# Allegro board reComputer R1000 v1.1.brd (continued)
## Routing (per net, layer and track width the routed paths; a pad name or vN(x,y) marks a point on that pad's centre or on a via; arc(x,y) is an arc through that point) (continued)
N23572410: length 5.1
  TOP w0.121: Q4.4 31.3,73.57 30.48,74.38 C162.2 29.98,75.91 R162.2 R163.2
N23572413: length 2.1
  TOP w0.121: Q5.3 27.51,74.71 R163.1
N23578952: length 2
  BOTTOM w0.121: U31.3 34.01,73.37 R173.1
N23579284:
  vias: v1(85.5,22.67) v1(85.5,22.19) v1(85.5,21.7) v1(85.93,30.24) v1(85.93,29.76) v1(85.93,29.27) v1(85.96,22.67) v1(85.96,22.19) v1(85.96,21.7) v1(86.39,30.24) v1(86.39,29.76) v1(86.39,29.27)
N23611485: length 2.6
  BOTTOM w0.121: R12.1 77.3,37.39 U1.4
N23611490: length 2.7
  BOTTOM w0.305: C15.1 68.51,39.27 69.12,38.66 U1.6
N23612078: length 13.3
  LYR6 w0.381: v1(76.18,41.2) 71.3,41.2 67.95,44.55 v1(67.95,46.46)
  BOTTOM w0.381: U1.1 v1(76.18,41.2) ; C5.1 v1(67.95,46.46)
N23612081: length 1.5
  BOTTOM w0.381: R9.1 65.66,44.98 C5.2
N23613464: length 3.1
  BOTTOM w0.381: D10.2 67.17,42.72 R9.2
N23613978: length 4.8
  BOTTOM w0.121: U1.3 76.75,38.66 R10.2 77.59,37.9 77.9,38.21 78.66,38.21 R8.2
N23614867: length 6.2
  BOTTOM w0.305: C17.2 64.9,39.35 R13.2 66.65,39.35 R14.1 68.18,38.37 69.17,37.39 U1.5
N23615765: length 1.2
  BOTTOM w0.508: R11.2 65.64,47.95 C16.1
N23616333: length 7.5
  LYR6 w0.381: v1(48.52,42.62) 52.85,42.62 v1(53.75,41.72)
  BOTTOM w0.381: C18.1 v1(48.52,42.62) ; v1(53.75,41.72) 54.26,41.21 U2.1
N23616335: length 1.5
  BOTTOM w0.381: C18.2 46.35,42.6 R15.1
N23616337: length 1.9
  BOTTOM w0.381: R15.2 47.91,41.21 U2.8
N23616378: length 4.6
  BOTTOM w0.121: U2.3 56.33,38.67 R17.2 56.4,38.71 56.64,38.95 57.31,38.95 R16.2 57.61,38.33 R181.2
N23616505: length 1.7
  BOTTOM w0.121: R19.1 56.39,37.4 U2.4
N23616509: length 3.8
  BOTTOM w0.305: U2.5 49.22,37.4 48.87,37.06 R21.1 48.35,38.02 R20.2 48.36,38.37 48.08,38.65 C30.2
N23616593: length 2.8
  BOTTOM w0.305: C28.1 48.08,40.1 48.61,39.57 48.61,38.96 48.9,38.67 U2.6
N23616615: length 1.3
  BOTTOM w0.508: C29.1 43.72,48.49 R18.2
N23711005: length 11.5
  BOTTOM w0.114: J8.A2 105.6,60.78 105.71,60.9 106.41,60.9 106.83,60.48 106.83,59.61 107.58,58.86 109.24,58.86 110.12,59.74 111.9,59.74 112.37,59.27 D15.2 112.42,59.29 112.88,59.75 114.02,59.75 L4.3
N23711301: length 11.5
  BOTTOM w0.114: L4.2 114.07,60.03 112.88,60.03 112.42,60.49 D14.2 112.35,60.5 111.88,60.02 110,60.02 109.12,59.14 107.7,59.14 107.11,59.73 107.11,60.59 106.53,61.17 105.71,61.17 105.6,61.29 J8.A3
N23763799:
  vias: v1(111.18,17.16) v1(111.13,16.19) v1(112.27,16.19) v1(112.32,17.16) v1(113.31,16.17) v1(113.36,17.13) v1(114.28,17.13)
N23781625: length 1.4
  BOTTOM w0.121: U33.6 28.72,34.11 R651.2
N23800931: length 0.9
  BOTTOM w0.305: R13.1 65.68,38.49 R652.2
N23801005: length 1.9
  BOTTOM w0.305: R653.2 46.49,38.67 47.09,38.67 47.43,38.33 R20.1
N23858113: length 5.9
  BOTTOM w0.508: 2.49,51.98 2.55,52.04 J24.22
  BOTTOM w0.762: FB26.1 3.12,47.85 2.26,48.7 2.26,51.75 2.49,51.98
N23912708: length 39.1
  TOP w0.121: R24.2 48.87,65.9 49.91,64.86 50.29,64.86 v1(50.75,65.32) ; J4.28 v1(68.6,72.07)
  LYR3 w0.121: v1(68.6,72.07) v1(68.6,66.71)
  BOTTOM w0.121: v1(50.75,65.32) 51.93,64.13 57.38,64.13 59.97,66.73 68.59,66.73 v1(68.6,66.71)

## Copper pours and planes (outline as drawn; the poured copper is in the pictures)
3V3_RS485 on TOP: 62.84,25.06 62.21,25.06 61.95,25.31 61.95,27.32 62.23,27.6 63.1,27.6 63.27,27.42 63.27,26.99 63.1,26.81 63.1,25.31
3V3_RS485 on LYR6: 84,23.86 63.17,23.86 62.18,24.85 62.18,26.73 62.56,27.11 76.91,27.11 78.92,25.11 84,25.11 84.23,24.88 84.23,24.09
5V_ISO_INPUT on TOP: 72.06,19.67 72.06,18.2 71.86,18 71.86,17.06 71.73,16.93 70.92,16.93 70.64,17.21 70.64,18.25 70.11,18.78 69.7,18.78 69.27,19.21 69.27,21.37 69.52,21.63 70.39,21.63 70.82,21.2 70.82,19.67 71.07,19.42 71.73,19.42 71.99,19.67
5V_ISO_OUT on TOP: 68.15,11.87 67.44,11.87 66.37,12.94 64.9,12.94 64.52,13.32 64.52,14.54 64.77,14.79 65.15,14.79 65.89,14.06 67.08,14.06 68.4,12.74 68.4,12.13
5V_ISO_OUT on LYR6: 86.77,9.31 71.88,9.31 68.48,12.71 66.78,12.71 66.27,13.22 62.94,13.22 62.82,13.09 62.41,13.09 62.28,13.22 62.28,16.24 63.4,17.36 67.74,17.36 69.5,15.61 90.4,15.61 91.47,16.67 92.38,16.67 92.66,16.39 92.66,15.2
5V_TYPC on TOP: 65.08,10.65 64.06,10.65 63.43,10.02 62.66,10.02 62.18,10.5 62.18,11.72 61.52,12.38 61.52,12.99 61.42,13.09 60.68,13.09 60.51,12.92 60.51,12.41 61.11,11.8 61.11,9.99 61.39,9.71 61.65,9.71 62.13,9.23 63.65,9.23 64.47,10.04 65.08,10.04 65.2,10.17 65.2,10.53
5V_TYPC on TOP: 60.71,2.2 60.71,2.6 61.17,3.06 61.17,3.92 60.94,4.15 60.15,4.15 59.84,3.85 59.84,3.11 59.57,2.83 59.18,2.83 59.03,2.68 59.03,2.12 59.18,1.97 60.48,1.97
5V_TYPC on BOTTOM: 10.92,34.81 9.73,34.81 9.63,34.91 9.63,35.29 9.73,35.39 10.04,35.39 10.62,35.98 11.25,35.98 11.41,35.83 11.41,35.29
5V_TYPC on LYR3: 65.05,6.03 63.76,6.03 63.43,6.36 62.36,6.36 62.11,6.11 62.11,2.86 61.7,2.45 59.92,2.45 59.59,2.78 59.59,6.16 60.48,7.05 60.48,12.79 60.66,12.97 61.42,12.97 61.67,12.71 61.67,10.98 62.74,9.92 63.32,9.92 64.06,10.65 65,10.65 65.2,10.45 65.2,6.18
5V_TYPC on LYR3: 39.3,54.11 39.3,52.82 35.59,49.11 29.9,49.11 28.91,48.12 28.91,39.97 31.04,37.83 31.04,31.61 35.11,27.55 35.11,21.27 34.62,20.79 33.71,20.79 33.17,21.32 33.17,26.38 28.81,30.75 28.81,36.41 26.32,38.9 26.32,46.62 27.13,47.43 27.13,49.26 28.53,50.66 33.35,50.66 34.14,51.45 34.14,55.18 34.44,55.49 37.92,55.49
5V_TYPC on LYR6: 9.12,35.72 9.12,37.35 9.88,38.11 28.78,38.11 29.01,37.88 29.01,36.92 28.76,36.66 11.56,36.66 11.38,36.49 11.38,35.7 11.2,35.52 9.32,35.52
5V_TYPC on LYR6: 33.99,23.41 42.85,23.41 43.74,22.52 48.41,22.52 49.94,20.99 60.73,20.99 61.72,20 61.72,12.08 61.52,11.87 59.9,11.87 59.31,12.46 59.31,17.66 57.89,19.09 44.73,19.09 42.22,21.6 33.89,21.6 33.66,21.83 33.66,23.08 ; 1 cut-out
+1.8V_OUT on TOP: 34.57,69 54.38,69 56.57,71.18 56.57,72.15 56.42,72.3 56.26,72.3 54.43,70.47 46.76,70.47 46.15,69.86 34.62,69.86 34.42,69.66 34.42,69.15
+1.8V_OUT on BOTTOM: 56.72,71.77 56.72,72.88 56.49,73.11 56.14,73.11 55.96,72.94 55.96,71.77 56.11,71.61 56.57,71.61
GND on TOP: outline of 150 points within 1.88,1.1 117.43,83.4 ; 35 cut-outs
GND on TOP: 32.41,49.49 34.27,49.49 34.6,49.16 34.6,46.6 33.99,45.99 32.31,45.99 32.08,46.21 32.08,49.16
GND on TOP: 104.83,51.4 104.29,51.4 103.81,50.91 102.29,50.91 101.83,51.37 101.45,51.37 100.61,50.53 98.91,50.53 98.58,50.2 98.58,47.56 98.78,47.36 99.65,47.36 99.88,47.59 99.88,48.35 100.36,48.83 103.1,48.83 103.91,49.64 103.91,50.3 104.35,50.74 104.83,50.74 105.01,50.91 105.01,51.22
GND on TOP: 32.03,52.18 32.03,58 31.19,58.84 8.49,58.84 7.42,57.77 7.42,48.93 6.99,48.5 5.84,48.5 5.69,48.65 5.69,55.87 4.96,56.6 3.48,56.6 3.03,57.06 3.03,57.72 3.38,58.08 5.06,58.08 7.98,61 25.1,61 26.16,59.93 31.12,59.93 32.62,58.43 32.62,52.31 32.41,52.11 32.11,52.11
GND on BOTTOM: 36.4,46.72 34.17,46.72 33.35,45.91 32.57,45.91 32.36,46.11 32.36,47.26 33.99,48.88 36.55,48.88 36.68,48.75 36.68,47
GND on BOTTOM: outline of 126 points within 1.88,1.1 117.43,83.4 ; 25 cut-outs
GND on BOTTOM: 16.08,20.48 16.08,20.05 15.78,19.75 15.19,19.75 15.04,19.9 15.04,20.61 15.22,20.79 15.78,20.79
GND on LYR2_GND: outline of 130 points within 1.88,1.1 117.43,83.4
GND on LYR4_GND: outline of 136 points within 1.88,1.1 117.43,83.4
GND on LYR7_GND: outline of 124 points within 1.88,1.1 117.43,83.4
GND_EARTH on TOP: outline of 106 points within 0.23,0.22 119.48,83.4
GND_EARTH on TOP: 10.04,20.87 8.77,20.87 8.51,21.12 8.51,22.82 8.79,23.1 10.04,23.1 10.34,22.8 10.34,21.17
GND_EARTH on BOTTOM: outline of 114 points within 0.23,0.22 119.48,83.4 ; 1 cut-out
GND_EARTH on LYR2_GND, LYR3: outline of 89 points within 0.23,0.22 119.48,83.4 ; 1 cut-out
GND_EARTH on LYR4_GND: outline of 127 points within 0.23,0.22 119.48,83.4
GND_EARTH on LYR5_PWR: outline of 117 points within 0.23,0.22 119.48,83.4 ; 1 cut-out
GND_EARTH on LYR6: outline of 125 points within 0.23,0.22 119.48,83.4 ; 2 cut-outs
GND_EARTH on LYR7_GND: outline of 123 points within 0.23,0.22 119.48,83.4 ; 2 cut-outs
GND_ISO on TOP: 57.61,22.16 58.17,22.16 58.83,21.5 61.52,21.5 64.87,18.15 70.11,18.15 70.39,17.87 70.39,16.57 71.02,15.94 100.56,15.94 100.99,15.51 100.99,3.82 100.1,2.93 68.33,2.93 68.1,3.16 68.1,5.7 69.52,7.12 69.52,9.56 68.71,10.38 67.74,10.38 67.46,10.65 67.46,12.48 66.78,13.17 64.49,13.17 64.24,12.92 63.81,12.92 63.65,13.07 62.54,13.07 62.31,13.3 62.31,14.24 57.43,19.11 57.43,21.98 ; 1 cut-out
GND_ISO on TOP: 59.26,18.96 58.98,18.96 58.12,19.82 58.12,21.88 57.81,22.19 56.24,22.19 55.91,21.86 55.91,19.87 58.14,17.64 59.18,17.64 59.41,17.87 59.41,18.81
GND_ISO on BOTTOM: 57.61,22.16 58.17,22.16 58.83,21.5 61.52,21.5 64.87,18.15 70.11,18.15 70.39,17.87 70.39,16.57 71.02,15.94 100.56,15.94 100.99,15.51 100.99,3.82 100.1,2.93 68.33,2.93 68.1,3.16 68.1,5.7 69.52,7.12 69.52,9.56 68.71,10.38 67.74,10.38 67.46,10.65 67.46,12.48 66.78,13.17 64.49,13.17 64.24,12.92 63.81,12.92 63.65,13.07 62.54,13.07 62.31,13.3 62.31,14.24 57.43,19.11 57.43,21.98 ; 1 cut-out
GND_ISO on LYR2_GND, LYR4_GND, LYR5_PWR, LYR7_GND: 57.61,22.16 58.17,22.16 58.83,21.5 61.52,21.5 64.87,18.15 70.11,18.15 70.39,17.87 70.39,16.57 71.02,15.94 100.56,15.94 100.99,15.51 100.99,3.82 100.1,2.93 68.33,2.93 68.1,3.16 68.1,5.7 69.52,7.12 69.52,9.56 68.71,10.38 67.74,10.38 67.46,10.65 67.46,12.48 66.78,13.17 64.49,13.17 64.24,12.92 63.81,12.92 63.65,13.07 62.54,13.07 62.31,13.3 62.31,14.24 57.43,19.11 57.43,21.98
GND_ISO on LYR3: 57.61,22.16 58.17,22.16 58.83,21.5 61.52,21.5 64.87,18.15 70.11,18.15 70.39,17.87 70.39,16.57 71.02,15.94 99.32,15.94 100.99,14.26 100.99,3.82 100.1,2.93 68.33,2.93 68.1,3.16 68.1,5.7 69.52,7.12 69.52,9.56 68.71,10.38 67.74,10.38 67.46,10.65 67.46,12.48 66.78,13.17 64.49,13.17 64.24,12.92 63.81,12.92 63.65,13.07 62.54,13.07 62.31,13.3 62.31,14.24 57.43,19.11 57.43,21.98
VCC_USB1 on TOP: 98.24,53.49 97.94,53.78 97.94,54.65 98.05,54.75 98.48,54.75 98.76,55.03 98.76,55.18 100.59,57.01 102.03,57.01 102.31,56.73 102.31,56.35 101.48,55.51 101.48,55.03 99.94,53.49
VCC_USB1 on TOP: 110.75,73.72 110.75,73.93 109.45,75.22 109.45,75.68 109.3,75.83 108.1,75.83 107.88,75.6 107.88,74.74 109.12,73.49 110.52,73.49
VCC_USB1 on LYR3: 100,53.68 98.22,53.68 98.05,53.86 98.05,56.58 106.71,65.24 106.71,75.3 107.11,75.7 109.45,75.7 109.88,75.27 109.88,59.35 108.66,58.13 104.45,58.13
VCC_USB2 on TOP: 105.97,51.24 105.54,51.24 105.08,51.7 104.02,51.7 103.56,51.24 102.34,51.24 101.96,51.62 101.27,51.62 101.12,51.78 101.12,52.69 101.2,52.77 104.09,52.77 104.32,52.54 105.97,52.54 106.2,52.31 106.2,51.47
VCC_USB2 on TOP: 109.6,70.24 110.77,70.24 111.58,71.06 113.52,71.06 113.74,70.83 113.74,69.94 113.44,69.63 109.71,69.63 109.55,69.79 109.55,70.19
VCC_USB2 on LYR3: 101.27,52.82 105.97,52.82 106.99,53.83 106.99,55.87 112.6,61.48 112.6,69.07 111.74,69.94 111.74,70.47 111.91,70.65 114.1,70.65 114.35,70.4 114.35,60.06 109.4,55.1 109.4,52.06 108.56,51.22 101.37,51.22 101.12,51.47 101.12,52.67
VDD33_HUB1 on TOP: 43.21,33.79 42.65,33.79 42.34,34.1 42.34,36.59 42.7,36.94 44.66,36.94 44.91,36.69 44.91,35.98 44.76,35.83 43.46,35.83 43.31,35.67 43.31,35.09 43.49,34.91 43.49,34.07
VDD33_HUB1 on TOP: 59.16,27.42 59.16,28.89 58.98,29.07 58.37,29.07 58.22,28.92 58.22,27.34 58.45,27.11 58.85,27.11
VDD33_HUB1 on LYR6: 56.67,38.42 45.27,38.42 42.29,35.44 42.29,30.59 43.18,29.7 57.13,29.7 58.27,28.56 59.01,28.56 59.29,28.84 59.29,32.27 58.6,32.96 45.47,32.96 45.16,33.26 45.16,33.62 46.92,35.37 56.62,35.37 57,35.75 57,38.09
VDD33_HUB2 on TOP: 101.12,73.7 101.4,73.7 101.88,74.18 102.52,74.18 102.75,73.95 102.75,72.94 102.54,72.73 101.27,72.73 100.99,73.01 100.99,73.57
VDD33_HUB2 on LYR3: 94.49,65.26 100.43,65.26 102.67,67.5 102.67,73.24 102.34,73.57 98.45,73.57 97.36,74.66 96.07,74.66 91.93,70.52 87.81,70.52 86.62,71.72 86.62,74.46 86.16,74.92 77.07,74.92 76.66,74.51 76.66,73.14 76.96,72.83 81.38,72.83 86.87,67.35 92.41,67.35
VDD33A_HUB1 on TOP: 57.28,26.07 57.53,26.33 57.53,28.82 57.25,29.09 56.75,29.09 55.63,27.98 54.41,27.98 54.28,27.85 54.28,27.6 54.41,27.47 54.76,27.47 55.55,26.68 55.55,26.2 55.68,26.07
VDD33A_HUB1 on LYR3: 57.36,28.46 56.59,28.46 55.55,29.5 55.55,32.55 55.76,32.75 56.77,32.75 57.53,31.99 57.53,28.64
VDD33A_HUB1 on LYR6: 46.13,25.46 45.32,25.46 45.16,25.62 45.16,26.66 47.2,28.69 52.56,28.69 52.91,28.33 55.83,28.33 56.44,28.94 57.48,28.94 57.74,28.69 57.74,26.53 56.21,25.01 51.26,25.01 51.11,25.16 51.11,25.54 50.88,25.77 46.43,25.77
VDD_3V3_PCIE on TOP: 20.78,68.97 20.78,69.73 20.63,69.89 19.71,69.89 19.56,69.73 19.56,68.95 19.74,68.77 20.58,68.77
VDD_3V3_PCIE on BOTTOM: 21.39,65.54 19.43,65.54 19.38,65.59 19.38,70.07 19.66,70.34 21.36,70.34 21.59,70.12 21.59,65.75
VDD_3V3_PCIE on BOTTOM: 19.2,47.48 19.2,48.53 21.74,51.07 21.74,52.62 21.54,52.82 16.92,52.82 16.28,52.18 16.28,50.13 15.06,48.91 15.06,47.64 15.39,47.31 19.03,47.31
VDD_3V3_PCIE on LYR3: 18.77,48.68 16.49,48.68 15.65,49.52 15.65,68.54 17.15,70.04 20.42,70.04 20.6,69.86 20.6,50.51
VDD_3V3_SYS on TOP: 74.37,24.83 72.29,24.83 72.06,25.06 72.06,25.77 72.27,25.97 74.32,25.97 74.53,25.77 74.53,24.98
VDD_3V3_SYS on TOP: 63.81,26.94 63.81,27.57 64.01,27.77 64.67,27.77 64.85,27.6 64.85,26.89 64.7,26.73 64.01,26.73
VDD_3V3_SYS on TOP: 15.05,5.35 15.05,6.31 15.2,6.46 16.39,6.46 16.51,6.34 16.51,5.3 16.31,5.09 15.31,5.09
VDD_3V3_SYS on TOP: 102.19,75.78 101.96,75.55 101.96,75.07 102.11,74.92 102.67,74.92 103.15,74.43 104.02,74.43 104.22,74.64 104.22,75.55 103.99,75.78
VDD_3V3_SYS on TOP: 27.59,70.95 23.42,70.95 23.17,70.7 23.17,70.12 23.35,69.94 25.89,69.94 25.99,70.04 25.99,70.22 26.16,70.4 26.8,70.4 27.16,70.75 27.59,70.75 27.66,70.83 27.66,70.88
VDD_3V3_SYS on TOP: 43.89,30.75 43.89,32.8 43.64,33.06 42.47,33.06 42.19,32.78 42.19,30.72 42.42,30.49 43.64,30.49
VDD_3V3_SYS on BOTTOM: 5.39,45.3 4.52,45.3 3.99,45.83 3.99,46.44 3.71,46.72 3.05,46.72 2.82,46.49 2.82,45.86 3.25,45.43 3.25,43.8 3.51,43.55 5.21,43.55 5.44,43.78 5.44,45.25
VDD_3V3_SYS on BOTTOM: 41.76,27.85 41.76,29.12 41.43,29.45 40.39,29.45 40.03,29.09 40.03,27.9 40.26,27.67 41.58,27.67
VDD_3V3_SYS on BOTTOM: 13.95,48.58 12.83,48.58 11.53,47.28 11.53,46.11 11.94,45.71 13.92,45.71 14.18,45.96 14.18,48.35
VDD_3V3_SYS on BOTTOM: 17.12,18.5 15.37,18.5 15.22,18.66 15.22,18.81 16.41,20 16.41,20.41 16.56,20.56 17.38,20.56 17.58,20.36 17.58,18.96
VDD_3V3_SYS on BOTTOM: 56.44,44.12 54.71,44.12 54.41,44.43 54.41,49.02 55.37,49.99 62.21,49.99 62.61,49.58 62.61,47.14 62.23,46.76 57.53,46.76 56.77,46 56.77,44.45
VDD_3V3_SYS on LYR5_PWR: outline of 84 points within 2.29,4.96 110.19,80.89
VDD_5V_OUT on TOP: 36.91,79.21 36.91,79.95 36.73,80.12 36.02,80.12 33.71,82.43 31.8,82.43 31.4,82.03 31.4,80.63 33.12,78.9 36.6,78.9
VDD_5V_OUT on BOTTOM: 33.91,74.97 36.38,74.97 36.68,75.27 36.68,75.55 36.93,75.81 36.93,79.74 36.68,80 34.67,80 33.71,79.03 33.71,75.17
VDD_5V_SYS on TOP: 56.44,75.46 56.44,76.14 56.16,76.42 52.38,76.42 51.79,77 51.79,78.96 52.17,79.34 53.75,79.34 54.51,78.57 56.75,78.57 57.99,77.33 58.63,77.33 58.73,77.23 58.73,75.51 58.63,75.41 58.45,75.41 58.45,76.12 58.42,76.15 58.37,76.15 58.35,76.12 58.35,75.41 58.04,75.41 58.04,76.12 58.02,76.15 57.97,76.15 57.94,76.12 57.94,75.41 57.66,75.41 57.66,76.12 57.64,76.15 57.58,76.15 57.56,76.12 57.56,75.41 57.25,75.41 57.25,76.12 57.23,76.15 57.18,76.15 57.15,76.12 57.15,75.41 56.85,75.41 56.85,76.12 56.82,76.15 56.77,76.15 56.75,76.12 56.75,75.41 56.49,75.41
VDD_5V_SYS on TOP: 110.67,72.76 109.35,72.76 108.99,73.11 108.38,73.11 108.16,72.88 108.16,72.12 108.44,71.84 108.99,71.84 109.35,72.2 110.67,72.2 110.77,72.3 110.77,72.66
VDD_5V_SYS on TOP: 99.98,52.84 100.74,52.84 100.84,52.74 100.84,51.95 100.69,51.8 100.05,51.8 99.88,51.98 99.88,52.74
VDD_5V_SYS on TOP: 72.14,21.68 71.66,21.68 70.61,22.72 69.95,22.72 69.62,23.05 69.62,25.49 69.83,25.69 70.69,25.69 70.89,25.49 70.89,24.01 71.27,23.63 72.01,23.63 72.24,23.41 72.24,21.78
VDD_5V_SYS on BOTTOM: 100.74,52.84 99.67,52.84 99.21,52.39 98.07,52.39 92.76,57.7 82.02,57.7 81.66,57.34 81.66,54.29 81.92,54.04 93.02,54.04 97.16,49.9 100.41,49.9 100.89,50.38 100.89,52.69
VDD_5V_SYS on BOTTOM: 76.28,43.88 74.96,43.88 74.55,44.28 74.55,48.3 75.92,49.67 81.59,49.67 82.22,49.03 82.22,47.61 81.97,47.36 81.38,47.36 80.67,46.65 77.09,46.65 76.76,46.32 76.76,44.36
VDD_5V_SYS on BOTTOM: 107.39,72.66 107.39,75.07 107.65,75.32 108.69,75.32 108.87,75.15 108.87,73.52 109.32,73.06 109.32,72.73 110.19,71.87 110.19,71.31 110.04,71.16 108.89,71.16
VDD_5V_SYS on BOTTOM: 27.16,73.85 26.62,73.85 25.5,74.97 25.1,74.97 24.79,74.66 24.79,74.08 25.94,72.94 27.21,72.94 27.38,73.11 27.38,73.62
VDD_5V_SYS on BOTTOM: 5.41,37.45 5.08,37.78 5.08,38.8 5.39,39.1 9.02,39.1 10.44,37.68 10.44,36.26 9.98,35.8 9.73,35.8 9.6,35.93 9.6,36.64 8.79,37.45
VDD_5V_SYS on LYR3: 6.43,38.21 6.43,41.92 15.04,50.53 15.04,68.9 18.7,72.55 18.7,73.32 18.37,73.65 15.7,73.65 10.87,68.82 10.87,50.41 4.37,43.9 4.37,38.21 4.73,37.86 6.07,37.86
VDD_5V_SYS on LYR3: 80.39,47.84 80.39,67.45 80.83,67.88 83.54,67.88 83.95,67.47 83.95,47.81 83.64,47.51 80.72,47.51
VDD_5V_SYS on LYR5_PWR: 81.69,56.45 81.69,57.97 82.22,58.51 98.43,58.51 99.93,60.01 99.93,68.13 101.09,69.3 102.8,69.3 103.41,69.91 103.41,71.84 104.83,73.27 108.97,73.27 109.53,72.71 109.53,66.46 110.54,65.44 114.45,65.44 117.25,62.65 117.25,59.5 115.8,58.05 105.49,58.05 103.63,56.2 81.94,56.2
VDD_5V_SYS on LYR5_PWR: 80.98,49.54 77.8,49.54 77.24,48.98 77.24,38.75 69.27,30.77 69.27,25.08 69.67,24.68 71.17,24.68 71.55,25.06 71.55,26.43 72.11,26.99 74.58,26.99 81.41,33.82 81.41,49.11
VDD_5V_SYS on LYR5_PWR: 82.6,66.59 78.11,66.59 77.68,67.02 77.68,68.13 76.23,69.58 43.94,69.58 42.06,67.7 37.21,67.7 33.68,71.23 17.88,71.23 17.17,71.94 17.17,75.7 19.87,78.4 65.03,78.4 68.84,74.59 70.44,74.59 70.45,74.57 79.75,74.57 82.98,71.34 82.98,66.97
VDD_IN on TOP: 67.54,30.59 67.24,30.59 67.06,30.42 67.06,26.96 67.59,26.43 71.25,26.43 71.81,26.99 71.81,30.09 71.27,30.62 69.78,30.62 69.6,30.44 69.6,28.23 69.55,28.18 69.09,28.18 69.04,28.23 69.04,30.47 68.89,30.62 68.48,30.62 68.33,30.47 68.33,28.28 68.25,28.21 67.87,28.21 67.77,28.31 67.77,30.36
VDD_IN on TOP: 29.39,76.31 29.85,76.31 30,76.47 30.89,76.47 31.22,76.14 31.22,74.79 31.47,74.54 32.46,74.54 32.57,74.64 32.57,75.04 32.46,75.15 31.85,75.15 31.8,75.2 31.8,75.75 31.85,75.81 32.46,75.81 32.57,75.91 32.57,76.31 32.46,76.42 31.88,76.42 31.83,76.47 31.83,77.02 31.93,77.13 32.51,77.13 32.59,77.2 32.59,78.85 32.24,79.21 29.87,79.21 29.24,78.57 29.24,76.47
VDD_IN on BOTTOM: 17.33,80.05 18.52,80.05 18.85,80.38 18.85,81.34 18.57,81.62 17.27,81.62 17.07,81.42 17.07,80.3
VDD_IN on BOTTOM: 64.8,53.33 42.37,53.33 42.24,53.45 42.24,53.89 44.58,56.22 55.45,56.22 56.31,55.36 64.8,55.36 65.05,55.1 65.05,53.58
VDD_IN on BOTTOM: 54.28,40.25 55.7,40.25 56.09,40.63 57.1,40.63 57.3,40.83 62.38,40.83 62.69,40.52 62.69,39.33 62.51,39.15 59.16,39.15 58.93,38.92 58.93,38.42 58.8,38.29 58.65,38.29 58.45,38.49 58.45,38.9 58.19,39.15 55.91,39.15 55.4,39.66 54.23,39.66 54.13,39.76 54.13,40.09
VDD_IN on BOTTOM: 74.83,40.22 76.25,40.22 76.43,40.4 85.83,40.4 86.24,39.99 86.24,38.11 85.63,37.5 80.06,37.5 79.86,37.71 79.86,38.14 79.56,38.44 77.29,38.44 76.1,39.64 74.81,39.64 74.68,39.76 74.68,40.07
VDD_IN on LYR3: 64.65,39.18 61.62,39.18 61.42,39.38 61.42,42.91 62.28,43.78 62.28,53.61 62.49,53.81 64.65,53.81 64.82,53.63 64.82,53.05 65.18,52.69 65.18,39.71
VDD_IN on LYR3: 31.96,79.21 34.93,79.21 39.19,74.94 39.19,71.72 43.21,67.7 43.21,53.58 42.93,53.3 40.85,53.3 40.49,53.66 40.49,65.14 34.88,70.75 34.88,71.59 31.52,74.94 31.52,78.78
VDD_IN on LYR6: 83.44,36.16 79.07,36.16 78.34,35.42 78.34,29.3 77.65,28.61 60.76,28.61 59.21,30.16 59.21,40.27 59.69,40.75 63.91,40.75 64.42,40.25 64.42,37.65 64.72,37.35 65.56,37.35 67.77,39.56 83.31,39.56 83.85,39.03 83.85,36.56
VDD_IN on LYR6: 32.21,79.11 21.14,79.11 18.87,81.37 17.22,81.37 16.97,81.11 16.97,79.16 19.76,76.36 32.31,76.36 32.59,76.64 32.59,78.73
VDD_LTE_3V3 on TOP: 77.93,30.97 77.93,29.91 76.94,28.92 76,28.92 75.44,28.36 75.44,27.04 75.16,26.76 73.51,26.76 73.26,27.01 73.26,29.09 74.15,29.98 74.73,29.98 75.82,31.08 75.82,31.97 79.4,35.55 79.4,36.03 79.53,36.16 80.85,36.16 81.1,35.9 81.1,34.15
VDD_LTE_3V3 on TOP: 106.53,31.99 106.53,33.82 106.76,34.05 108,34.05 108.26,33.79 108.26,31.97 108.1,31.81 106.71,31.81
VDD_LTE_3V3 on TOP: 33.56,65.19 35.71,65.19 35.97,65.44 35.97,66 35.84,66.13 33.61,66.13 33.35,65.87 33.35,65.39
VDD_LTE_3V3 on BOTTOM: 107.34,33.08 104.27,33.08 103.1,34.25 103.1,35.98 103.33,36.21 103.84,36.21 104.7,35.34 108.18,35.34 108.31,35.22 108.31,34.73 108.21,34.63 107.75,34.63 107.5,34.38 107.5,33.24
VDD_LTE_3V3 on BOTTOM: 80.11,36.13 79.61,36.13 79.02,35.55 79.02,33.92 79.23,33.72 80.06,33.72 80.29,33.95 80.29,35.95
VDD_LTE_3V3 on LYR3: 78.72,33.72 78.36,34.07 78.36,44.51 75.49,47.38 75.49,66.79 75.8,67.09 78.72,67.09 79,66.81 79,48.75 81.18,46.57 81.18,34.96 79.94,33.72
VDD_LTE_3V3 on LYR5_PWR: 42.98,65.14 34.95,65.14 34.57,65.52 34.57,67.02 34.9,67.35 42.34,67.35 44.25,69.25 75.82,69.25 77.19,67.88 77.19,66.92 76.86,66.59 75.47,66.59 75.11,66.94 44.78,66.94
VDD_LTE_3V3 on LYR6: 79.58,25.62 107.32,25.62 108.49,26.78 108.49,34.76 107.55,35.7 79.4,35.7 78.97,35.27 78.97,26.22
VDD_OUT on TOP: 35.44,77.66 36.43,77.66 37.29,78.52 37.29,79.95 36.53,80.71 36.53,81.93 37.01,82.41 38.86,82.41 39.32,81.95 39.32,74.13 38.48,73.29 35.21,73.29 34.62,73.88 34.62,76.85
VDD_OUT on BOTTOM: 37.54,76.47 37.54,75.7 37.82,75.42 39.6,75.42 40.72,76.54 40.72,78.7 40.52,78.9 40.21,78.9 40.03,78.73 40.03,76.57 39.96,76.49 39.55,76.49 39.45,76.59 39.45,79.41 38.84,80.02 37.82,80.02 37.49,79.69 37.49,76.52
VDD_UPS on TOP: 67.08,32.37 67.08,35.32 67.74,35.98 71.55,35.98 73.46,37.88 75.52,37.88 78.35,40.72 78.35,43.43 78.74,43.83 83.09,43.83 83.49,43.42 83.49,40.45 79.48,36.44 78.67,36.44 75.16,32.93 73.79,32.93 73.05,32.19 69.78,32.19 69.6,32.37 69.6,34.51 69.55,34.56 69.12,34.56 69.04,34.48 69.04,32.35 68.89,32.19 68.43,32.19 68.33,32.3 68.33,34.53 68.28,34.58 67.87,34.58 67.77,34.48 67.77,32.35 67.62,32.19 67.26,32.19
VDD_UPS on BOTTOM: 82.65,41.46 82.43,41.69 82.43,44.13 83.04,44.74 83.9,44.74 84.03,44.87 84.03,48.14 84.48,48.6 87.53,48.6 87.94,48.2 87.94,42.89 86.51,41.46
EXT_VCC_9_36V on TOP: 96.67,31.1 90.86,31.1 90.4,31.56 90.4,36.44 91.19,37.22 92.61,37.22 94.03,38.65 94.03,41.49 94.62,42.07 97.16,42.07 97.67,41.57 97.67,32.09
EXT_VCC_9_36V on BOTTOM: 97.41,40.55 95.48,40.55 91.7,44.33 91.7,45.15 91.26,45.58 88.98,45.58 88.85,45.71 88.85,46.11 88.95,46.21 89.56,46.21 89.61,46.27 89.61,46.8 89.56,46.85 88.9,46.85 88.83,46.93 88.83,47.36 88.95,47.48 89.56,47.48 89.64,47.56 89.64,48.04 89.56,48.12 89,48.12 88.83,48.3 88.83,48.78 89.03,48.98 91.98,48.98 92.38,48.58 92.38,47.23 92.71,46.9 94.24,46.9 97.67,43.47 97.67,40.8
EXT_VCC_9_36V on LYR3: 105.51,17.56 105.51,23.99 96.04,33.46 95.07,33.46 94.62,33.01 94.62,27.37 99.77,22.21 99.77,17.44 100.38,16.83 104.78,16.83
HDMI0_5V on TOP: 98.38,47.46 98.38,51.17 98.2,51.35 97.18,51.35 97.03,51.19 97.03,47.48 97.28,47.23 98.15,47.23
HDMI0_5V on LYR3: 101.27,41.21 98.3,41.21 95.56,43.95 95.56,48.09 95.96,48.5 97.69,48.5 97.89,48.3 97.89,47.43 97.34,46.87 97.34,44.67 98.22,43.78 101.42,43.78 101.7,43.5 101.7,41.64
ISO_5V on TOP: 58.98,16.5 65.23,16.5 65.43,16.29 65.43,15.63 65.23,15.43 58.88,15.43 58.7,15.61 58.7,16.22
LORA_3V3 on BOTTOM: 53.52,23.79 53.52,27.8 53.32,28 53.11,28 52.99,27.88 52.99,26.1 52.94,26.05 52.76,26.05 52.71,26.1 52.71,27.85 52.58,27.98 52.35,27.98 52.17,27.8 52.17,26.1 50.55,24.47 50.55,23.68 50.78,23.46 53.19,23.46
LORA_3V3 on BOTTOM: 71.02,34.12 71.02,36.66 71.17,36.82 71.63,36.82 72.16,36.28 72.16,32.93 71.53,32.3 59.26,32.3 58.98,32.57 58.98,36.05 59.13,36.21 59.34,36.21 59.51,36.03 59.51,34.07 59.82,33.77 70.67,33.77
LORA_3V3 on BOTTOM: 42.98,26.91 40.59,26.91 40.39,26.71 40.39,25.95 40.64,25.69 43,25.69 43.23,25.92 43.23,26.66
LORA_3V3 on LYR5_PWR: 51.31,23.35 42.04,23.35 41.48,23.91 41.48,26.94 44.02,29.48 44.02,35.39 44.25,35.62 59.64,35.62 59.97,35.29 59.97,33.62 51.69,25.34 51.69,23.74
POE_12V on TOP: 35.84,44.87 31.35,44.87 27.66,41.19 27.66,39.79 28.32,39.13 34.83,39.13 36.3,40.6 36.3,44.41
POE_12V on BOTTOM: 54.76,50.74 54.21,50.18 43.49,50.18 40.36,47.05 40.36,44.41 38.03,42.07 34.32,42.07 33.58,42.81 33.58,45.68 34.27,46.37 36.78,46.37 37.06,46.65 37.06,48.45 41.63,53.02 92.84,53.02 95.1,50.76 95.1,47.74 94.62,47.26 93.04,47.26 92.69,47.61 92.69,49.57 91.52,50.74
POE_IN_N on TOP: 11.61,9.64 12.6,9.64 12.96,9.28 14.46,9.28 14.73,9 14.73,7.78 14.28,7.33 11.51,7.33 11.23,7.61 11.23,9.26
POE_IN_N on TOP: 23.07,16.22 19.99,16.22 19.74,16.47 19.74,17.74 20.27,18.27 21.95,18.27 23.07,19.39 23.07,21.91 23.4,22.24 25.86,22.24 26.16,21.93 26.16,19.19 25.33,18.35 25.2,18.35
POE_IN_N on TOP: 30.74,17.18 30.74,15.12 31.32,14.54 33.78,14.54 34.19,14.95 34.19,17.28 33.71,17.77 31.32,17.77
POE_IN_N on BOTTOM: 26.67,18.33 25.45,18.33 25.15,18.63 25.15,19.77 25.35,19.98 26.7,19.98 26.9,19.77 26.9,18.55
POE_IN_N on LYR3: 33.66,14.57 33.25,14.57 31.35,16.47 26.37,16.47 25,17.84 25,19.72 25.25,19.98 27.03,19.98 28.17,18.83 33.51,18.83 33.99,18.35 33.99,14.9
POE_IN_N on LYR6: 21.11,17.94 19.54,17.94 19.23,17.64 19.23,16.17 18.98,15.91 15.29,15.91 12,12.62 12,8.58 12.42,8.17 14.73,8.17 15.09,8.52 15.09,10.38 18.18,13.46 19.52,13.46 21.36,15.3 21.36,17.69
POE_IN_N1 on TOP: 40.01,15.33 36.15,15.33 34.85,16.62 34.85,23.05 33.76,24.14 28.43,24.14 27.94,24.62 27.94,25.67 28.3,26.02 36.25,26.02 37.32,24.95 37.32,20.31 40.44,17.18 40.44,15.76
POE_IN_P on TOP: 20.98,15.07 21.57,15.66 23.37,15.66 24.67,16.95 24.67,18.05 25.07,18.45 25.86,18.45 26.06,18.25 26.06,14.44 25.3,13.68 18.37,13.68 14.35,9.66 13.16,9.66 12.58,10.25 10.42,10.25 9.98,9.82 9.98,8.88 9.5,8.39 9.1,8.39 8.82,8.67 8.82,11.77 10.39,13.35 15.85,13.35 17.05,14.54 17.91,14.54 18.44,15.07
POE_IN_P1 on TOP: 38.08,21.78 38.08,25.64 37.06,26.66 27.43,26.66 26.44,27.65 13.41,27.65 12.22,26.45 12.22,24.78 11.66,24.22 8.18,24.22 7.62,24.78 7.62,25.82 10.92,29.12 37.72,29.12 41.63,25.21 41.63,21.86 41.15,21.37 38.48,21.37
UART_3V3 on TOP: 60.63,5.57 60.63,7.1 60.4,7.33 58.45,7.33 58.24,7.12 58.24,6.31 58.37,6.18 58.73,6.18 59.57,5.35 60.4,5.35
USBA_GND on TOP: 105.41,65.21 114.23,65.21 114.71,65.7 115.27,65.7 115.55,65.42 115.55,64.15 115.27,63.87 105.39,63.87 105.13,64.12 105.13,64.93
USBA_GND on BOTTOM: 115.32,65.77 114.81,65.77 114.1,65.06 114.1,63.87 114.48,63.49 115.17,63.49 115.55,63.87 115.55,65.54
USIM_1V8 on TOP: 33.25,67.04 31.68,67.04 31.42,67.3 31.42,68.39 31.73,68.69 32.79,68.69 33.1,69 33.1,69.35 33.23,69.48 33.94,69.48 34.11,69.3 34.11,68.85 33.56,68.29 33.56,67.35
USIM_VDD on TOP: 31.78,55.97 31.78,57.75 31.57,57.95 31.09,57.95 30.84,57.7 30.84,55.99 31.07,55.76 31.57,55.76
N21116206 on BOTTOM: 102.77,24.78 106.94,24.78 109.45,22.26 112.12,22.26 112.68,21.7 112.68,19.85 110.09,17.26 110.09,9.36 108.79,8.06 108.79,6.57 108.44,6.21 107.47,6.21 107.06,6.62 107.06,9.41 107.6,9.94 107.6,18.73 105.64,20.69 102.72,20.69 102.01,21.4 102.01,24.01
N21116211 on TOP: 80.6,21.2 79.23,21.2 78.01,22.41 76.25,22.41 75.87,22.8 75.87,24.75 76.43,25.31 78.39,25.31 80.62,27.55 109.45,27.55 110.14,28.23 110.14,35.01 110.77,35.65 113.01,35.65 113.29,35.37 113.29,34.48 112.63,33.82 112.63,24.95 112.12,24.45 82.6,24.45 81.21,23.05 81.21,21.81
N21116390 on TOP: 84.08,16.73 85.47,16.73 86.74,18 89.54,18 90.25,17.28 95,17.28 95.48,17.77 95.48,19.77 94.97,20.28 85.52,20.28 83.54,18.3 83.54,17.26
N21116390 on BOTTOM: 92,19.49 97.61,19.49 99.37,21.25 99.37,23.86 98.55,24.68 97.31,24.68 94.72,22.08 91.82,22.08 91.39,21.65 91.39,20.1
N21392725 on BOTTOM: 4.42,36.05 9.22,36.05 9.35,35.93 9.35,34.2 9.12,33.97 7.8,33.97 6.96,34.81 4.45,34.81 4.24,35.01 4.24,35.88
N21411651 on TOP: 58.96,20.08 60.84,20.08 61.78,19.14 67.41,19.14 67.74,19.47 67.74,21.53 67.34,21.93 66.6,21.93 66.3,21.63 66.3,21.17 65.97,20.84 62.44,20.84 61.72,21.55 58.88,21.55 58.6,21.27 58.6,20.43
N21629438 on TOP: 96.75,43.8 96.75,46.77 96.4,47.13 94.9,47.13 94.64,46.87 94.64,43.88 94.92,43.6 96.55,43.6
N22027038 on TOP: 22.58,23.38 21.92,23.38 21.72,23.58 21.72,25.34 23.78,27.39 24.11,27.39 24.34,27.16 24.34,26.4 22.79,24.85 22.79,23.58
N22027038 on TOP: 20.42,19.75 20.42,18.71 20.58,18.55 21.47,18.55 21.92,19.01 21.92,19.75 21.74,19.93 20.6,19.93
N22027038 on BOTTOM: 22.13,22.24 21.54,22.24 21.36,22.41 21.36,23.71 21.64,23.99 22.48,23.99 22.66,23.81 22.66,23.48 22.3,23.13 22.3,22.41
N22027038 on LYR3: 21.82,18.76 21.11,18.76 20.88,18.99 20.88,21.86 21.67,22.64 21.67,23.74 21.85,23.91 22.74,23.91 22.96,23.68 22.96,22.39 22.13,21.55 22.13,19.06
N22027110 on TOP: 8.87,18.38 9.91,18.38 10.06,18.53 10.06,19.72 9.91,19.87 8.87,19.87 8.69,19.7 8.69,18.55
N22027110 on TOP: 17.71,22.34 17.05,22.34 16.84,22.54 16.84,26.45 17.86,27.47 18.34,27.47 18.47,27.34 18.47,26.48 17.96,25.97 17.96,22.59
N22027110 on LYR6: 9.53,19.19 8.92,19.19 8.69,19.42 8.69,20.84 11.58,23.74 12.4,23.74 12.91,24.24 17.66,24.24 17.96,23.94 17.96,22.72 17.55,22.31 12.65,22.31
N22027117 on TOP: 20.96,22.31 20.3,22.31 20.09,22.52 20.09,26.63 20.91,27.44 21.29,27.44 21.41,27.32 21.41,26.45 21.21,26.25 21.21,22.57
N22027117 on TOP: 16.72,19.75 16.72,18.71 16.87,18.55 18.06,18.55 18.21,18.71 18.21,19.75 18.04,19.93 16.89,19.93
N22027117 on LYR3: 21.01,23.66 18.95,23.66 18.49,23.2 18.49,22.44 17.43,21.37 17.43,18.99 17.66,18.76 18.72,18.76 18.95,18.99 18.95,21.27 20.3,22.62 20.91,22.62 21.14,22.85 21.14,23.53
N22028382 on TOP: 14.46,22.19 13.79,22.19 13.59,22.39 13.59,26.07 14.84,27.32 15.09,27.32 15.22,27.19 15.22,26.33 14.71,25.82 14.71,22.44
N22028382 on TOP: 11.28,18.33 12.32,18.33 12.47,18.48 12.47,19.67 12.32,19.82 11.28,19.82 11.1,19.65 11.1,18.5
N22028382 on BOTTOM: 11.2,19.37 12.27,19.37 12.44,19.53 12.42,19.54 12.42,20.66 14.81,23.05 14.81,23.43 14.53,23.71 13.03,23.71 11.1,21.78 11.1,19.47
N22028488 on TOP: 19.36,19.87 18.67,19.87 18.47,19.67 18.47,18.58 14.89,15 13.9,15 13.67,14.77 13.67,13.98 13.87,13.78 15.75,13.78 19.26,17.28 19.26,17.87 19.61,18.22 19.61,19.62
N22028491 on TOP: 15.67,19.93 14.99,19.93 14.66,19.6 14.66,18.17 13.77,17.28 13.77,16.73 14.15,16.34 15.52,16.34 15.95,16.78 15.95,19.65
N22029929 on TOP: 29.64,14.9 27.99,14.9 27.64,15.25 27.64,22.82 28.25,23.43 32.62,23.43 33.17,22.87 33.17,20.61 32.67,20.1 31.02,20.1 30.25,19.34 30.25,15.51
N22029929 on BOTTOM: 28.83,18.58 28.83,19.9 28.55,20.18 27.84,20.18 27.64,19.98 27.64,18.55 27.87,18.33 28.58,18.33
N22038032 on TOP: 14.48,21.73 13.59,21.73 12.96,22.36 12.04,22.36 11.74,22.06 11.74,20.71 12.14,20.31 14.51,20.31 14.68,20.48 14.68,21.53
N22038032 on TOP: 17.71,21.73 16.82,21.73 16.59,21.5 16.59,20.99 16.82,20.76 17.68,20.76 17.91,20.99 17.91,21.53
N22038032 on TOP: 20.91,21.73 20.02,21.73 19.79,21.5 19.79,20.99 20.02,20.76 20.88,20.76 21.11,20.99 21.11,21.53
N22038032 on BOTTOM: 21.97,21.86 20.09,21.86 19.81,21.58 19.81,20.97 20.02,20.76 22.08,20.76 22.23,20.92 22.23,21.6
N22038032 on LYR6: 20.27,20.76 15.12,20.76 14.58,20.23 13.08,20.23 12.83,20.48 12.83,21.68 13.13,21.98 20.22,21.98 20.42,21.78 20.42,20.92
N23452929 on TOP: 108.05,51.37 107.19,51.37 106.94,51.62 106.94,52.46 107.5,53.02 107.5,57.85 107.7,58.05 108.56,58.05 108.84,57.77 108.84,52.16
N23572753 on BOTTOM: 26.88,74.69 31.55,74.69 31.88,75.02 31.88,75.88 31.55,76.21 26.7,76.21 26.42,75.93 26.42,75.15
N23579284 on TOP: 96.42,17.28 96.42,19.93 95.43,20.92 83.85,20.92 83.31,21.45 83.31,23.53 83.75,23.96 98.53,23.96 100.1,22.39 100.1,17.36 99.52,16.78 96.93,16.78
N23579284 on TOP: 89.92,30.64 85.83,30.64 85.52,30.34 85.52,29.25 85.88,28.89 90.1,28.89 90.43,29.22 90.43,30.14
N23579284 on LYR3: 88.62,21.5 83.7,21.5 83.14,22.06 83.14,28.38 85.3,30.54 88.62,30.54 89.33,29.83 89.33,22.21
N23613464 on BOTTOM: 70.51,40.88 67.46,40.88 67.11,41.24 67.11,42.71 68.33,43.93 68.33,47.18 67.97,47.54 66.98,47.54 66.8,47.71 66.8,48.48 67.11,48.78 69.9,48.78 70.79,47.89 70.79,41.16
N23616337 on BOTTOM: 50.17,40.95 49.13,40.95 48.8,41.28 48.8,43.03 48.01,43.82 46.76,43.82 46.31,44.27 46.31,48.49 46.71,48.9 49.84,48.9 50.6,48.13 50.6,41.38
N23763799 on TOP: 109.81,1.76 103.1,1.76 101.53,3.34 101.53,20.61 104.14,23.23 112.22,23.23 113.49,24.5 113.49,32.93 115.09,34.53 115.09,36.94 115.62,37.48 117.53,37.48 118.04,36.97 118.04,33.92 116.79,32.68 116.79,31.56 116.82,31.53 116.82,18.96 113.52,15.66 105.97,15.66 104.63,14.31 104.63,10.22 105.82,9.03 108.61,9.03 109.53,8.11 109.53,3.54 110.26,2.81 110.26,2.22
N23860408 on TOP: 18.42,3.69 18.42,4.56 18.21,4.76 17.4,4.76 16.97,5.19 16.97,6.26 17.07,6.36 17.71,6.36 18.9,5.17 18.9,3.59 18.82,3.52 18.6,3.52
N23869571 on TOP: 99.04,51.95 97.16,51.95 96.9,52.21 96.9,52.79 97.11,53 99.06,53 99.21,52.84 99.21,52.13
N234528750 on TOP: 105.97,56.83 104.4,56.83 103.61,57.62 101.48,57.62 101.3,57.8 101.3,58.74 101.5,58.94 104.17,58.94 104.93,58.18 105.92,58.18 106.17,57.92 106.17,57.03

Small or netless copper shapes (teardrops, artwork), in the pictures only: 2 on TOP

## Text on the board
Ref Des/Assembly Bottom: Assembly_Bottom
Ref Des/Silkscreen Bottom: DSI | TPM | M.2_KEY_M | V1.1 | reComputer R | AC:12-24V | DC:9-36V | PCIe2 | Mini | PCIe1
Ref Des/Assembly Top: Assembly_Top
Ref Des/Silkscreen Top: BOOT | NOR | UPS | GNDI | 3B | 3A | 2B | 2A | 1B | PE | 1A | DISPLAY | USBA | LED | POE | ETH0/1G/POE | ETH1/100M | USBC | SIM | RST | RTC
PAGE_OUTLINE: W:5/S:7 | W:4/S:8
User.45: FIGURE | FINISHED_SIZE | 8.0 | 15.75 | 21.65 | 31.5 | 35.43 | 36.0 | 39.37 | 40.0 | 43.31 | 47.24 | 51.18 | 55.12 | 57.09 | 59.06 | 63.0 | 90.55 | 122.05 | 146.85 | 165.35 | 169.29 | 41.34 | 62.99 | 66.93 | 127.95 | 128.0 | 29.53x21.65 | 43.31x19.69 | 70.87x19.69 | 106.3x35.43 | ROTATION | - | 90.000 | 0.000 | DRILL CHART: TOP to BOTTOM | ALL UNITS ARE IN MILS | SLOT HOLES: TOP to BOTTOM | TOLERANCE_DRILL | +0.0/-0.0 | +3.0/-3.0 | +1.97/-1.97 | +5.0/-5.0 | PLATED | NON-PLATED | QTY | 1791 | 4 | 14 | 2 | 19 | 6 | 8 | 1 | 7 | 12 | 9 | 1940 | TOTAL HOLES:
